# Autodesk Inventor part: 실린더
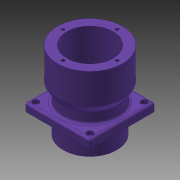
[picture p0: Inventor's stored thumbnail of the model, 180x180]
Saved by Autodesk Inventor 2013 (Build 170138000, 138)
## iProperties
Created: 2016-11
Part Number: 실린더
Material: 알루미늄 6061
Document SubType Name: Modeling
Designer: mduedu
Density: 2.71 g/cm^3
Mass: 568.286 g
Surface Area: 557.364 cm^2
Volume: 209.7 cm^3
Author: mduedu
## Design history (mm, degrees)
sketch "스케치1"
  geometry: L1 (0, 0)-(0, 101); L2 (30, 0)-(30, 101); L3 (30, 101)-(42, 101); L4 (42, 101)-(42, 61); L5 (42, 61)-(35, 51); L6 (35, 51)-(35, 0); L7 (35, 0)-(30, 0)
  constraints: 14 end point, 4 parallel, 2 horizontal alignment, 1 perpendicular, 1 vertical
  dimensions: "d0" = 101 distance of L1.start L1.end; "d1" = 60 diameter of L2.end L1; "d2" = 84 diameter of L3.end L1; "d3" = 70 diameter of L6.end L1; "d4" = 40 distance of L3.end L4.end; "d5" = 50 vertical distance of L5.end L3.end
revolve "회전1" sketch "스케치1" stored, may be unused: angle "d6" = 90 deg
node "작업 평면1"
sketch "스케치2"
  geometry: L1 (-42.5, -42.5)-(42.5, -42.5); L2 (42.5, -42.5)-(42.5, 42.5); L3 (42.5, 42.5)-(-42.5, 42.5); L4 (-42.5, 42.5)-(-42.5, -42.5); L5 (-42.5, -42.5)-(42.5, 42.5); L6 (42.5, -42.5)-(-42.5, 42.5); C1 r 35 at (0, 0) reference; C2 r 35 at (0, 0); 1 further point
  constraints: 12 end point, 2 midpoint, 2 parallel, 2 perpendicular, 1 centre point, 1 coincident, 1 concentric, 1 horizontal
  dimensions: "d8" = 85 distance of L2.end L3.end
extrude "돌출1" join sketch "스케치2" distance "d10" = 10; taper "d11" = 0 deg
fillet "모깎기1" dims "d12" = 3
fillet "모깎기2" dims "d13" = 3
chamfer "모따기1" distance "d14" = 1; stored, may be unused: second distance "d15" = 2, angle "d16" = 45 deg
chamfer "모따기2" distance "d17" = 5; stored, may be unused: second distance "d18" = 2, angle "d19" = 15 deg
sketch "스케치3"
  geometry: L1 (-35, -35)-(35, -35); L2 (35, -35)-(35, 35); L3 (35, 35)-(-35, 35); L4 (-35, 35)-(-35, -35); L5 (-35, -35)-(35, 35); L6 (35, -35)-(-35, 35); 5 further points
  constraints: 12 end point, 4 coincident, 2 midpoint, 2 parallel, 1 horizontal, 1 perpendicular
  dimensions: "d20" = 70 distance of L3.end L2.end; "d21" = 70 distance of L2.end L1.end
sketch "스케치4"
  geometry: 4 further points
  constraints: 4 other
hole "구멍1" sketch "스케치4" at (-35, 35), (35, 35), (35, -35), (-35, -35) diameter "d22" = 4.5; stored, may be unused: countersink angle "d26" = 90 deg, drill point angle "d28" = 0 deg; dims "d23" = 6, "d24" = 8, "d25" = 4.6, "d27" = 8
sketch "스케치5"
  geometry: 4 further points
  constraints: 4 other
hole "구멍2" sketch "스케치5" at (0, -35), (35, 0), (-35, 0), (0, 35) diameter "d29" = 4.134; stored, may be unused: countersink angle "d33" = 90 deg, drill point angle "d35" = 120 deg; dims "d30" = 12, "d31" = 4, "d32" = 2, "d34" = 15
node "솔리드1"
other parameters: "d7" = -27
